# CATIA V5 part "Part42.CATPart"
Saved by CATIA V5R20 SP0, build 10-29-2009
Part number: FA 042200-3
Revision: ANY
Definition: UNKNOWN
Nomenclature: FA 042200-3
Source: Unknown
Bounding box of the stored display mesh (mm): x 0 to 2, y -1.45 to 1.45, z -1.45 to 1.45
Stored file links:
  C:\Users\Utente\Desktop\IO LAVORO\3D X SITO CF\CUMSA\3D files FA\FA 042200\Part42.CATPart

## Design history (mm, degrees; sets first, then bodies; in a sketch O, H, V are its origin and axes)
Body1 "Revolución1" (main body)
  Solid1: solid without history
